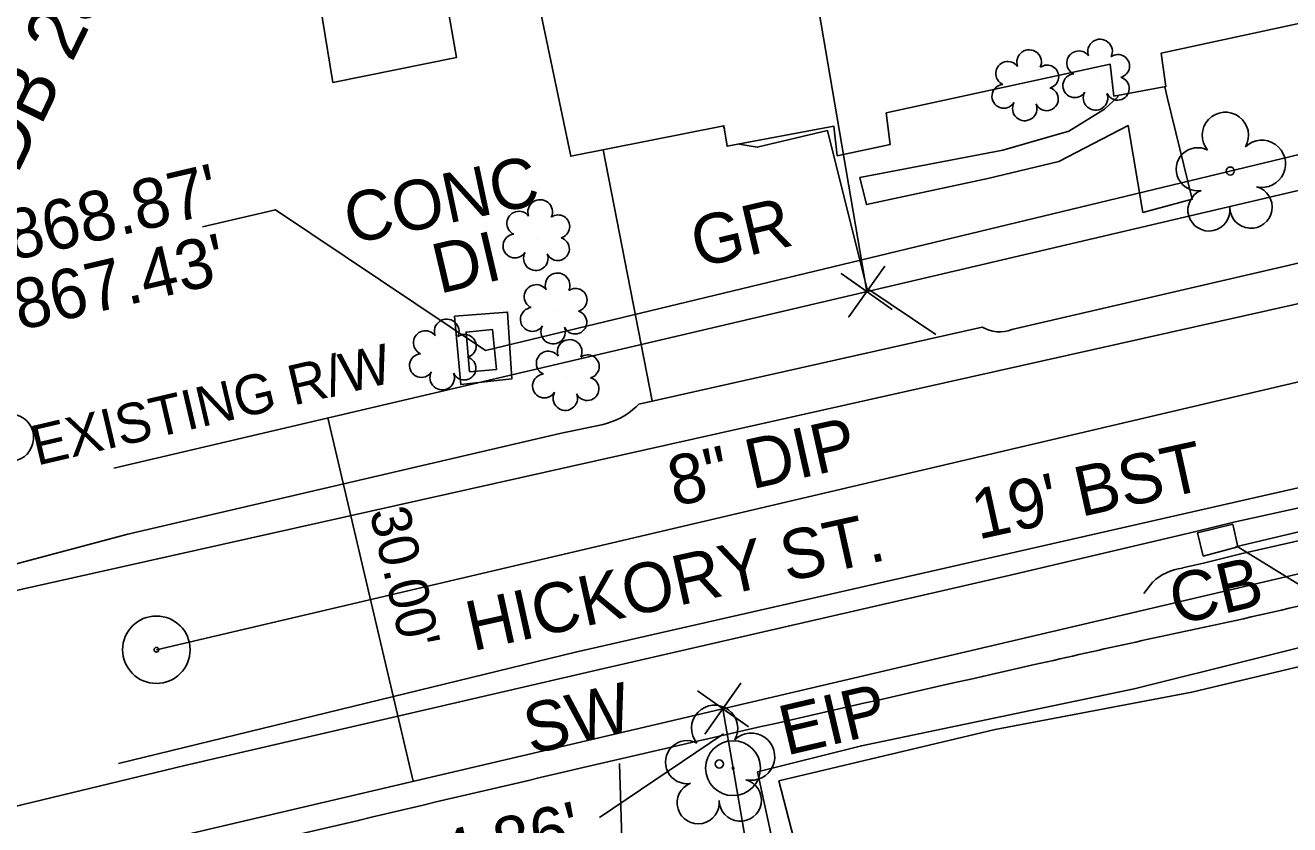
# Model space of a CAD drawing. Extents: x 553786 to 558838, y 502329 to 507342.
# Drawn here: x 557197.7 to 557299.3, y 506618.9 to 506683.2 of the extents above; entities that cross this region are included whole.
import ezdxf

# ---------------------------------------------------------------- set-up
doc = ezdxf.new("R2010")
doc.units = 0
for name, color, linetype in [('Exist Property Deed Book Text', 7, 'Continuous'), ('Exist Property Iron Pin Text', 7, 'Continuous'), ('Exist Property Owner Text', 7, 'Continuous'), ('Exist Right of Way Line Text', 7, 'Continuous'), ('Exist Right of Way Width CELL', 7, 'Continuous'), ('Exist Roads EOP Other Text', 7, 'Continuous'), ('Exist Roads EOP Text', 7, 'Continuous'), ('Exist Roads Soil Text', 7, 'Continuous'), ('Exist Structure Minor Catch Basin', 7, 'Continuous'), ('Exist Structure Minor Catch Basin Leader', 7, 'Continuous'), ('Exist Structure Minor Catch Basin Text', 7, 'Continuous'), ('Exist Structure Minor Drop Inlet', 7, 'Continuous'), ('Exist Structure Minor Drop Inlet Text', 7, 'Continuous'), ('Exist Structure Minor Drop Inlet Top Elevation', 7, 'Continuous'), ('Exist Structure Minor Paved Ditch or Gutter Text', 7, 'Continuous'), ('Exist Structure Minor Pipes CMP 18 Inch', 7, 'Continuous'), ('Exist Structure Minor Pipes HDPE 12 Inch', 7, 'Continuous'), ('Exist Structure Minor Pipes HDPE 12 Inch Invert', 7, 'Continuous'), ('Exist Structure Minor Pipes HDPE 12 Inch Leader', 7, 'Continuous'), ('Exist Utilities Sanitary Sewer UG Line', 7, 'Continuous'), ('Exist Utilities Sanitary Sewer UG Line Text', 7, 'Continuous'), ('Exist Vegetation Shrub CELL', 7, 'Continuous'), ('Exist Vegetation Tree CELL', 7, 'Continuous'), ('Prop CMT DNC', 7, 'Continuous'), ('Prop CMT Slope Grass', 7, 'Continuous'), ('Prop Drainage Structure Catch Basin Grate 840 03E Label', 7, 'Continuous'), ('Prop Drainage Structure Pipe Alternate 24in', 7, 'Continuous'), ('Prop Drainage Structure Pipe Alternate 36in', 7, 'Continuous'), ('Prop Drainage Structure Pipe Plug CELL', 7, 'Continuous'), ('Prop Drainage Structure Pipe Plug Label', 7, 'Continuous'), ('Prop Drainage Structure Pipe RCP 15in Class III Label', 7, 'Continuous'), ('Prop Drainage Structure Pipe RCP 15in Class IV', 7, 'Continuous'), ('Prop Drainage Structure Plot Symbol 50 Scale', 7, 'Continuous'), ('Prop Drainage Structure Tops and Inverts LABEL', 7, 'Continuous'), ('Prop Earthen Structure Tail Ditch Label', 7, 'Continuous'), ('Prop Earthen Structure V Ditch Lateral Detail Label', 7, 'Continuous'), ('Prop Erosion Rip Rap Pad Outlet for Jurisdictional Stream CELL', 7, 'Continuous'), ('Prop Erosion Rip Rap Single Stone CELL', 7, 'Continuous'), ('Prop Geopak Pavement Shape Independent', 7, 'Continuous'), ('Prop XS SE Text', 7, 'Continuous'), ('Sheet Layout Plan Border', 7, 'Continuous')]:
    doc.layers.add(name, color=color, linetype=linetype)

# ---------------------------------------------------------------- blocks, each defined once
blk = doc.blocks.new('EXIST PROPERTY IRON PIN')
at = {"layer": 'Prop Drainage Structure Pipe RCP 15in Class IV'}
for radius in [0.0441, 0.00141]:
    blk.add_circle((0, 0), radius, dxfattribs=at)
blk = doc.blocks.new('EXIST SURVEY CENTERLINE POINT')
at = {"layer": 'Prop Drainage Structure Catch Basin Grate 840 03E Label'}
for radius in [0.0542, 0.00375]:
    blk.add_circle((0, 0), radius, dxfattribs=at)

msp = doc.modelspace()

# ---------------------------------------------------------------- linework, layer by layer
at = {"layer": 'Exist Right of Way Width CELL'}
for p in [(557222.01, 506651.61), (557228.86, 506622.41)]:
    msp.add_line(p, (557225.49, 506636.77), dxfattribs=at)
at = {"layer": 'Exist Structure Minor Catch Basin'}
msp.add_lwpolyline([(557292.35, 506640.51), (557295.12, 506641.25), (557294.72, 506643.07), (557291.9, 506642.38), (557292.35, 506640.51)], dxfattribs=at)
at = {"layer": 'Exist Structure Minor Catch Basin Leader'}
msp.add_lwpolyline([(557295.12, 506641.25), (557316.01, 506628.38), (557321.85, 506629.75)], dxfattribs=at)
at = {"layer": 'Exist Structure Minor Drop Inlet'}
msp.add_lwpolyline([(557233.39, 506655.33), (557235.55, 506655.52), (557235.24, 506658.73), (557233.12, 506658.51), (557233.39, 506655.33)], dxfattribs=at)
at = {"layer": 'Exist Structure Minor Pipes CMP 18 Inch'}
msp.add_line((557427.08, 506672.79), (557294.95, 506641.24), dxfattribs=at)
at = {"layer": 'Exist Structure Minor Pipes HDPE 12 Inch'}
msp.add_line((557416.42, 506700.81), (557234.67, 506657.04), dxfattribs=at)
at = {"layer": 'Exist Structure Minor Pipes HDPE 12 Inch Leader'}
msp.add_lwpolyline([(557234.67, 506657.04), (557217.79, 506668.35), (557211.95, 506666.98)], dxfattribs=at)
at = {"layer": 'Exist Utilities Sanitary Sewer UG Line'}
msp.add_line((557161.84, 506629.9), (557366.26, 506675.61), dxfattribs=at)
at = {"layer": 'Exist Vegetation Shrub CELL'}
for p, q in [((557283.83, 506679.03), (557283.83, 506679.03)), ((557278.14, 506678.18), (557278.14, 506678.18)), ((557238.84, 506666.13), (557238.84, 506666.13)), ((557240.24, 506660.23), (557240.24, 506660.23)), ((557231.33, 506656.53), (557231.33, 506656.53)), ((557241.21, 506654.88), (557241.21, 506654.88))]:
    msp.add_line(p, q, dxfattribs=at)
for centre, radius, start, end in [((557284.06, 506681.07), 0.99, 334.8391, 200.4717), ((557278.36, 506680.22), 0.99, 334.8391, 200.4717), ((557282.35, 506680.15), 0.968, 35.8908, 245.4216), ((557276.65, 506679.3), 0.968, 35.8908, 245.4216), ((557279.81, 506679.05), 0.929, 284.4567, 126.0861), ((557285.5, 506679.9), 0.929, 284.4567, 126.0861), ((557282.03, 506678.32), 0.955, 95.1099, 327.9534), ((557285.47, 506678.1), 0.937, 204.9913, 73.4601), ((557276.33, 506677.47), 0.955, 95.1099, 327.9534), ((557279.77, 506677.25), 0.937, 204.9913, 73.4601), ((557278.01, 506676.49), 0.984, 151.2797, 21.387), ((557283.7, 506677.34), 0.984, 151.2797, 21.387), ((557239.07, 506668.17), 0.99, 334.8391, 200.4717), ((557237.36, 506667.26), 0.968, 35.8908, 245.4216), ((557240.52, 506667), 0.929, 284.4567, 126.0861), ((557237.04, 506665.43), 0.955, 95.1099, 327.9534), ((557240.48, 506665.2), 0.937, 204.9913, 73.4601), ((557238.72, 506664.45), 0.984, 151.2797, 21.387), ((557240.47, 506662.27), 0.99, 334.8391, 200.4717), ((557238.76, 506661.36), 0.968, 35.8908, 245.4216), ((557241.91, 506661.1), 0.929, 284.4567, 126.0861), ((557238.44, 506659.53), 0.955, 95.1099, 327.9534), ((557241.88, 506659.3), 0.937, 204.9913, 73.4601), ((557229.85, 506657.66), 0.968, 35.8908, 245.4216), ((557231.56, 506658.57), 0.99, 334.8391, 200.4717), ((557240.11, 506658.55), 0.984, 151.2797, 21.387), ((557233, 506657.4), 0.929, 284.4567, 126.0861), ((557241.44, 506656.92), 0.99, 334.8391, 200.4717), ((557229.53, 506655.83), 0.955, 95.1099, 327.9534), ((557239.73, 506656.01), 0.968, 35.8908, 245.4216), ((557242.89, 506655.75), 0.929, 284.4567, 126.0861), ((557232.97, 506655.6), 0.937, 204.9913, 73.4601), ((557231.2, 506654.85), 0.984, 151.2797, 21.387), ((557239.41, 506654.18), 0.955, 95.1099, 327.9534), ((557242.85, 506653.95), 0.937, 204.9913, 73.4601), ((557241.09, 506653.2), 0.984, 151.2797, 21.387)]:
    msp.add_arc(centre, radius, start, end, dxfattribs=at)
at = {"layer": 'Exist Vegetation Tree CELL'}
for p, q in [((557294.52, 506671.46), (557294.52, 506671.46)), ((557253.47, 506623.79), (557253.47, 506623.79))]:
    msp.add_line(p, q, dxfattribs=at)
for centre in [(557294.52, 506671.46), (557253.47, 506623.79)]:
    msp.add_circle(centre, 0.326, dxfattribs=at)
for centre, radius, start, end in [((557294.13, 506674.33), 1.86, 330.1651, 219.7134), ((557297.07, 506672.04), 1.9, 257.1011, 134.1999), ((557291.91, 506671.61), 1.73, 62.6636, 279.3457), ((557292.81, 506668.33), 1.69, 111.5671, 6.231), ((557296.19, 506668.56), 1.7, 181.2822, 74.56), ((557196.47, 506650.03), 1.9, 257.1011, 134.1999), ((557253.09, 506626.66), 1.86, 330.1651, 219.7134), ((557256.02, 506624.38), 1.9, 257.1011, 134.1999), ((557250.87, 506623.94), 1.73, 62.6636, 279.3457), ((557251.77, 506620.67), 1.69, 111.5671, 6.231), ((557255.15, 506620.89), 1.7, 181.2822, 74.56)]:
    msp.add_arc(centre, radius, start, end, dxfattribs=at)
at = {"layer": 'Prop CMT DNC'}
for p, q in [((557265.31, 506661.77), (557265.31, 506661.77)), ((557253.75, 506628.24), (557253.75, 506628.24))]:
    msp.add_line(p, q, dxfattribs=at)
for points in [[(557267.35, 506660.32), (557263.27, 506663.22), (557265.31, 506661.77), (557263.87, 506659.73), (557266.76, 506663.81)], [(557251.7, 506629.68), (557255.79, 506626.8), (557253.75, 506628.24), (557255.19, 506630.29), (557252.31, 506626.2)]]:
    msp.add_lwpolyline(points, dxfattribs=at)
at = {"layer": 'Prop CMT Slope Grass'}
msp.add_lwpolyline([(557316.25, 506637.18), (557286.8, 506629.84), (557264.89, 506625.26), (557256.54, 506623.15), (557259.37, 506610.05), (557260.18, 506606.22), (557260.47, 506599.29), (557263.44, 506591.4), (557265.33, 506579.62), (557266.97, 506572.61), (557270.59, 506560.28), (557269.26, 506551.89), (557272.75, 506534.27), (557275.36, 506521.21), (557277.56, 506499.14), (557278.41, 506495.18), (557277.09, 506491.56), (557277.96, 506487.23), (557281.47, 506481.41), (557281.86, 506473.81), (557285.7, 506459.3), (557286.63, 506457.24), (557305.09, 506458.11)], dxfattribs=at)
at = {"layer": 'Prop Drainage Structure Pipe Alternate 24in'}
msp.add_lwpolyline([(557205.19, 506623.83), (557241.9, 506632.77), (557297.73, 506645.49), (557342.19, 506655.52), (557379.47, 506664.05), (557420.96, 506673.1), (557469.65, 506683.24), (557504.08, 506691.4), (557523.18, 506696.86), (557533.62, 506697.3), (557538.85, 506694.82), (557541.91, 506691.86), (557543.89, 506686.56)], dxfattribs=at)
at = {"layer": 'Prop Drainage Structure Pipe Alternate 36in'}
for p, q in [((557274.6, 506658.91), (557246.99, 506652.72)), ((557246.99, 506652.72), (557246.78, 506652.5))]:
    msp.add_line(p, q, dxfattribs=at)
for points in [[(557205.94, 506642.27), (557186.61, 506637.13), (557178.18, 506635.58), (557173.53, 506635.12), (557169.54, 506635.72), (557166.7, 506636.64), (557164.13, 506637.82), (557161.89, 506639.51), (557159.79, 506641.38), (557157, 506644.63), (557154.74, 506647.84), (557153.25, 506650.68), (557150.25, 506659.52), (557146.74, 506680.8), (557144.48, 506700.55), (557143.29, 506710.73), (557141.31, 506727.51), (557139.32, 506748.07), (557136.95, 506760.7), (557135.8, 506768.68)], [(557516.88, 506694.42), (557484.11, 506686.6), (557449.11, 506678.48), (557428.31, 506673.57), (557425.31, 506672.8), (557414.94, 506670.36), (557382.4, 506663.12), (557348.32, 506655.29), (557313.04, 506647.26), (557294.81, 506643.23), (557291.75, 506642.48), (557277.09, 506639.04), (557243.83, 506631.4), (557210.53, 506623.68)], [(557359.72, 506679.08), (557343.94, 506674.88), (557308.86, 506666.13), (557276.97, 506658.72)], [(557244.12, 506651.09), (557240.65, 506650.36), (557205.94, 506642.27)], [(557139.19, 506607.12), (557142.41, 506607.91), (557158.24, 506611.16), (557172.11, 506614.58), (557192.17, 506619.24), (557210.53, 506623.68)]]:
    msp.add_lwpolyline(points, dxfattribs=at)
for centre, major_axis, ratio, start_param, end_param in [((557275.97, 506661.19), (2.62, -0.49), 0.997451, 4.355418, 5.281464), ((557242.82, 506656.77), (5.5, 1.94), 0.998542, 4.59949, 5.121735)]:
    msp.add_ellipse(centre, major_axis=major_axis, ratio=ratio, start_param=start_param, end_param=end_param, dxfattribs=at)
at = {"layer": 'Prop Drainage Structure Pipe Plug Label'}
msp.add_line((557253.79, 506626.22), (557243.83, 506619.49), dxfattribs=at)
at = {"layer": 'Prop Drainage Structure Pipe RCP 15in Class III Label'}
for p, q in [((557204.81, 506647.58), (557576.37, 506734.73)), ((557131.57, 506599.59), (557546.86, 506696.99))]:
    msp.add_line(p, q, dxfattribs=at)
at = {"layer": 'Prop Drainage Structure Plot Symbol 50 Scale'}
msp.add_spline([(557546.82, 506691.06), (557545.79, 506691.27), (557542.77, 506691.81), (557539.62, 506691.56), (557529.48, 506689.45), (557518.91, 506687.16), (557485.73, 506679.35), (557450.97, 506671.07), (557428.25, 506665.66), (557416.71, 506663.04), (557384.25, 506655.82), (557350.02, 506647.96), (557314.55, 506639.92), (557294.97, 506635.34), (557286.93, 506633.6), (557278.79, 506631.78), (557245.32, 506624.15), (557211.96, 506616.3)], degree=3, dxfattribs=at)
at = {"layer": 'Prop Drainage Structure Tops and Inverts LABEL'}
msp.add_line((557288.29, 506638.43), (557287.57, 506637.49), dxfattribs=at)
msp.add_lwpolyline([(557539.02, 506696.52), (557530, 506694.7), (557526.98, 506694.12), (557517.71, 506691.95), (557484.69, 506684.06), (557449.77, 506675.97), (557428.85, 506671.08), (557425.91, 506670.38), (557415.41, 506667.86), (557382.9, 506660.65), (557348.93, 506652.83), (557313.47, 506644.79), (557295.37, 506640.68), (557292.37, 506639.95), (557290.68, 506639.55)], dxfattribs=at)
msp.add_ellipse((557291.08, 506635.66), major_axis=(-3.82, -1.43), ratio=0.953935, start_param=4.467919, end_param=5.126232, dxfattribs=at)
at = {"layer": 'Prop Earthen Structure Tail Ditch Label'}
msp.add_lwpolyline([(557289.26, 506678.24), (557289.49, 506677.3), (557291.47, 506669.19), (557287.5, 506668.14), (557286.33, 506675.11), (557280.74, 506672.23), (557275.04, 506670.86), (557265.29, 506668.76), (557264.77, 506670.94), (557276.25, 506673.15), (557281.54, 506674.68), (557284.41, 506676.44), (557285.49, 506677.44), (557285.47, 506677.55)], dxfattribs=at)
at = {"layer": 'Prop Earthen Structure V Ditch Lateral Detail Label'}
for points in [[(557253.78, 506675.09), (557253.87, 506674.86)], [(557255.05, 506673.63), (557256.52, 506673.38), (557262.17, 506674.72), (557265.31, 506662.04), (557270.87, 506658.33)], [(557248.07, 506653), (557244.14, 506673.17)], [(557404.1, 506475.84), (557391.23, 506485.05), (557386.39, 506487.59), (557379.17, 506469.48), (557360.2, 506465.03), (557332.72, 506464.15), (557303.44, 506460.1), (557287.68, 506459.13), (557283.39, 506478.08), (557280.17, 506495.26), (557278.21, 506517.11), (557274.88, 506533.76), (557272.08, 506545.84), (557271.94, 506558.78), (557270.78, 506570.04), (557265.46, 506593.75), (557262.06, 506607.72), (557258.26, 506622.45), (557275.64, 506626.56), (557291.43, 506629.58), (557314.74, 506635.11), (557334.57, 506640.23), (557354.15, 506644.67), (557374.37, 506649.18)], [(557245.45, 506623.83), (557245.82, 506611.75), (557247.2, 506593.75), (557243.99, 506593.42)]]:
    msp.add_lwpolyline(points, dxfattribs=at)
at = {"layer": 'Prop Erosion Rip Rap Pad Outlet for Jurisdictional Stream CELL'}
for points in [[(557299.83, 506707.59), (557248.87, 506696.64), (557249.39, 506694.9), (557237.42, 506692.35), (557241.53, 506672.65), (557253.83, 506675.1), (557254.09, 506673.45), (557262.67, 506675.06), (557262.94, 506672.69), (557267.2, 506673.6), (557266.88, 506676.13), (557284.88, 506680.04), (557285.17, 506677.49), (557289.34, 506678.25), (557288.98, 506680.95), (557304.61, 506684.32)], [(557228.78, 506700.95), (557232.35, 506680.6), (557222.42, 506678.59), (557219.1, 506698.96)]]:
    msp.add_lwpolyline(points, close=True, dxfattribs=at)
at = {"layer": 'Prop Erosion Rip Rap Single Stone CELL'}
msp.add_lwpolyline([(557232.19, 506659.79), (557236.45, 506660.12), (557236.8, 506654.77), (557232.7, 506654.29), (557232.19, 506659.79)], dxfattribs=at)
at = {"layer": 'Prop XS SE Text'}
for p, q in [((557265.31, 506661.77), (557246.03, 506775.22)), ((557253.75, 506628.24), (557254.57, 506623.46)), ((557254.57, 506623.46), (557286.29, 506439.65))]:
    msp.add_line(p, q, dxfattribs=at)
at = {"layer": 'Sheet Layout Plan Border'}
msp.add_line((557208.23, 506632.98), (557608.72, 506726.91), dxfattribs=at)

# ---------------------------------------------------------------- block references
at = {"layer": 'Prop Drainage Structure Pipe RCP 15in Class IV', "xscale": 50, "yscale": 50}
msp.add_blockref('EXIST PROPERTY IRON PIN', (557254.57, 506623.46), dxfattribs=at)
at = {"layer": 'Prop Geopak Pavement Shape Independent', "xscale": 50, "yscale": 50}
msp.add_blockref('EXIST SURVEY CENTERLINE POINT', (557208.23, 506632.98), dxfattribs=at)

# ---------------------------------------------------------------- texts
at = {"layer": 'Exist Property Deed Book Text'}
msp.add_text('DB 259 PG 41', height=4.5, rotation=63.9318, dxfattribs=at).set_placement((557197.03, 506671.1))
at = {"layer": 'Exist Property Iron Pin Text'}
msp.add_text('EIP', height=4, rotation=13.2, dxfattribs=at).set_placement((557258.84, 506624.46))
at = {"layer": 'Exist Property Owner Text'}
msp.add_text('BETTY J. CARTER, ', height=5, rotation=63.9318, dxfattribs=at).set_placement((557177.97, 506674.08))
at = {"layer": 'Exist Right of Way Line Text'}
msp.add_text('EXISTING R/W', height=3.2, rotation=13.2, dxfattribs=at).set_placement((557198.63, 506647.77))
at = {"layer": 'Exist Right of Way Width CELL'}
msp.add_text("30.00'", height=3.2, rotation=283.2, dxfattribs=at).set_placement((557225.34, 506644.08))
at = {"layer": 'Exist Roads EOP Other Text'}
msp.add_text('SW', height=4, rotation=13.2411, dxfattribs=at).set_placement((557238.31, 506624.55))
at = {"layer": 'Exist Roads EOP Text'}
msp.add_text("HICKORY ST.     19' BST", height=4, rotation=12.4559, dxfattribs=at).set_placement((557233.63, 506632.85))
at = {"layer": 'Exist Roads Soil Text'}
msp.add_text('GR', height=4, rotation=13.2, dxfattribs=at).set_placement((557251.75, 506663.68))
at = {"layer": 'Exist Structure Minor Catch Basin Text'}
msp.add_text('CB', height=4, rotation=13.2, dxfattribs=at).set_placement((557290.19, 506634.96))
at = {"layer": 'Exist Structure Minor Drop Inlet Text'}
msp.add_text('DI', height=4, rotation=13.2, dxfattribs=at).set_placement((557230.97, 506661.58))
at = {"layer": 'Exist Structure Minor Drop Inlet Top Elevation'}
msp.add_text("TOP=1868.87'", height=4, rotation=13.2, dxfattribs=at).set_placement((557180, 506660.33))
at = {"layer": 'Exist Structure Minor Paved Ditch or Gutter Text'}
msp.add_text('CONC', height=4, rotation=12.0008, dxfattribs=at).set_placement((557223.81, 506665.57))
at = {"layer": 'Exist Structure Minor Pipes HDPE 12 Inch Invert'}
msp.add_text("INV=1867.43'", height=4, rotation=13.2, dxfattribs=at).set_placement((557182.62, 506655.21))
at = {"layer": 'Exist Utilities Sanitary Sewer UG Line Text'}
msp.add_text('8" DIP', height=4, rotation=12.6041, dxfattribs=at).set_placement((557249.86, 506644.48))
at = {"layer": 'Prop Drainage Structure Pipe Plug CELL'}
msp.add_text("4.86'", height=4, rotation=13.2, dxfattribs=at).set_placement((557231.53, 506614.33))

doc.saveas('drawing.dxf')
